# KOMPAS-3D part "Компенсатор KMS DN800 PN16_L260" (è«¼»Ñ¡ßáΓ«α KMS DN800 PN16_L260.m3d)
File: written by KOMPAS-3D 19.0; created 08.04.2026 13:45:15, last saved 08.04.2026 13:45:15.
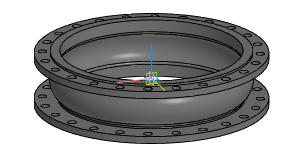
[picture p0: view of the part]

Document properties: Автор: Энергия; Полное имя файла: Z:\3.Личные\kachalov\3d для проектировщиков\7.1 Компенсатор\stp_Компенсатор KSM\Компенсатор KMS DN800 PN16_L260.m3d

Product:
- Part/product: Компенсатор KMS DN800 PN16_L260

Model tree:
1. Операция без истории:1  (labels: Компенсатор KMS DN800 PN16_L260)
